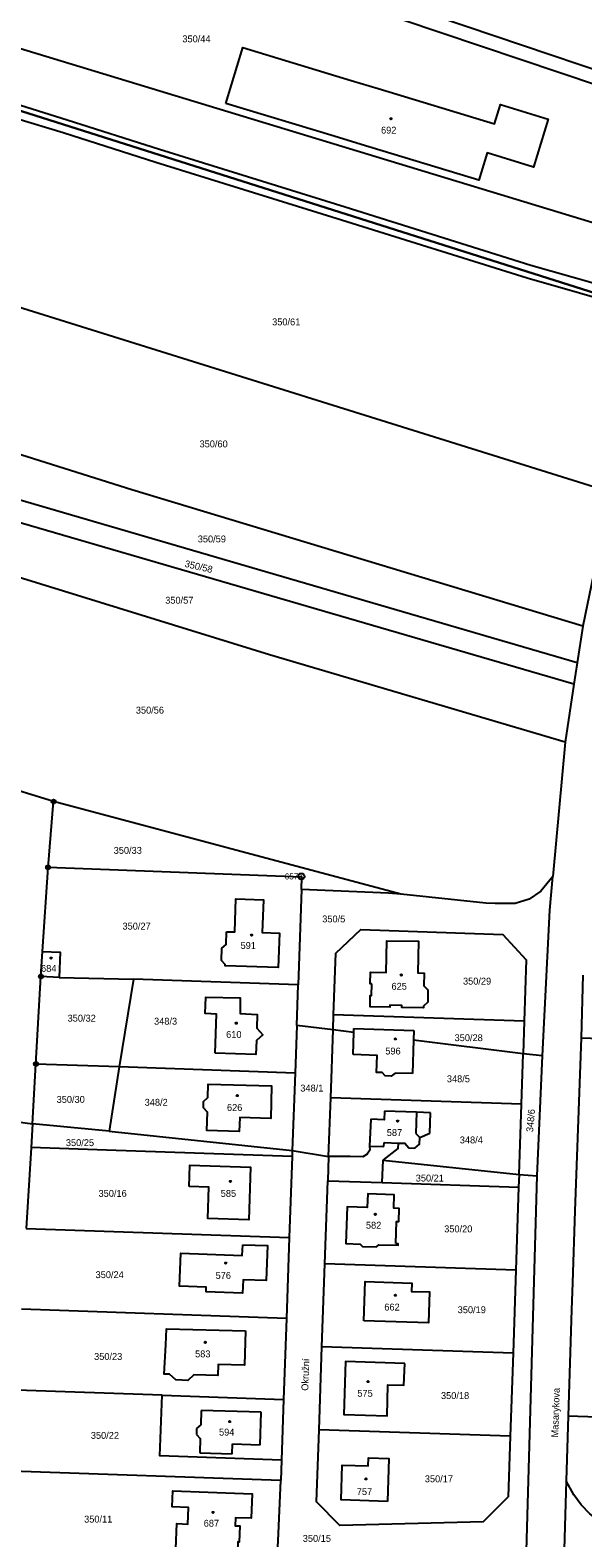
# Model space of a CAD drawing. Extents: x -758582 to -751794, y -998770 to -994350.
# Drawn here: x -756048.6 to -755912.3, y -995169.4 to -994797.3 of the extents above; entities that cross this region are included whole.
import ezdxf

# ---------------------------------------------------------------- set-up
doc = ezdxf.new("R2010")
doc.units = 0
for name, color, linetype in [('Hranice parcel', 7, 'Continuous'), ('Parcelní čísla', 7, 'Continuous'), ('Pop  PČ popisy', 7, 'Continuous'), ('Vnitřní kresba', 7, 'Continuous'), ('Věcná břemena k části', 7, 'Continuous'), ('Značky bodu BP', 7, 'Continuous'), ('Značky budov', 7, 'Continuous')]:
    doc.layers.add(name, color=color, linetype=linetype)

msp = doc.modelspace()

# ---------------------------------------------------------------- linework, layer by layer
at = {"layer": 'Hranice parcel'}
for p, q in [((-755905.48, -994911.3), (-756086.25, -994854.78)), ((-755913.68, -994953.37), (-756093.96, -994900.74)), ((-755914.5, -994958.67), (-756094.86, -994906.09)), ((-755905.48, -994911.3), (-755912.3, -994944.36)), ((-755912.3, -994944.36), (-755913.68, -994953.37)), ((-755913.68, -994953.37), (-755914.5, -994958.67)), ((-755914.5, -994958.67), (-755916.67, -994973.02)), ((-756042.86, -994987.64), (-756105.33, -994968.45)), ((-755916.67, -994973.02), (-755919.67, -995006.16)), ((-756044.23, -995003.89), (-756042.86, -994987.64)), ((-755957.2, -995010.51), (-756042.86, -994987.64)), ((-756045.56, -995024.64), (-756044.23, -995003.89)), ((-755981.6, -995006.33), (-756044.23, -995003.89)), ((-755981.7, -995009.33), (-755982.53, -995032.9)), ((-755981.7, -995009.33), (-755981.6, -995006.33)), ((-755919.67, -995006.16), (-755922.67, -995009.76)), ((-756045.98, -995030.81), (-756045.56, -995024.64)), ((-756047.22, -995052.41), (-756045.98, -995030.81)), ((-756041.52, -995031.03), (-756045.98, -995030.81)), ((-756041.52, -995031.03), (-756023.16, -995031.47)), ((-756023.16, -995031.47), (-756026.66, -995053.14)), ((-755982.53, -995032.9), (-756023.16, -995031.47)), ((-755912.26, -995030.46), (-755912.72, -995045.92)), ((-755982.88, -995042.87), (-755982.53, -995032.9)), ((-755982.88, -995042.87), (-755983.29, -995054.66)), ((-755973.91, -995043.99), (-755982.88, -995042.87)), ((-755973.91, -995043.99), (-755973.78, -995040.24)), ((-755926.77, -995041.81), (-755973.78, -995040.24)), ((-755926.77, -995041.81), (-755927.04, -995049.89)), ((-755974.49, -995060.72), (-755973.91, -995043.99)), ((-755968.8, -995044.63), (-755973.91, -995043.99)), ((-755968.98, -995050.08), (-755968.8, -995044.63)), ((-755968.8, -995044.63), (-755968.77, -995043.68)), ((-755968.77, -995043.68), (-755953.96, -995044.17)), ((-755954.04, -995046.49), (-755954.32, -995054.78)), ((-755953.96, -995044.17), (-755954.04, -995046.49)), ((-755927.04, -995049.89), (-755954.04, -995046.49)), ((-755927.45, -995062.29), (-755927.04, -995049.89)), ((-755922.21, -995050.42), (-755927.04, -995049.89)), ((-755923.55, -995079.97), (-755922.21, -995050.42)), ((-756048.07, -995067.15), (-756047.22, -995052.41)), ((-756026.66, -995053.14), (-756047.22, -995052.41)), ((-756026.66, -995053.14), (-756029.12, -995068.97)), ((-755983.29, -995054.66), (-756026.66, -995053.14)), ((-755983.29, -995054.66), (-755983.96, -995073.75)), ((-755975, -995075.23), (-755974.49, -995060.72)), ((-755927.45, -995062.29), (-755974.49, -995060.72)), ((-756082.85, -995062.35), (-756048.07, -995067.15)), ((-755950.03, -995069.45), (-755949.86, -995064.47)), ((-755928.03, -995079.68), (-755927.45, -995062.29)), ((-756048.07, -995067.15), (-756048.42, -995072.99)), ((-756029.12, -995068.97), (-756048.07, -995067.15)), ((-756029.12, -995068.97), (-755983.96, -995073.75)), ((-756048.42, -995072.99), (-756049.59, -995092.97)), ((-756029.84, -995073.65), (-756048.42, -995072.99)), ((-755984.01, -995075.25), (-756029.84, -995073.65)), ((-755984.01, -995075.25), (-755984.71, -995095.24)), ((-755983.96, -995073.75), (-755984.01, -995075.25)), ((-755983.96, -995073.75), (-755975, -995075.23)), ((-755975, -995075.23), (-755975.21, -995081.21)), ((-755969.65, -995075.27), (-755975, -995075.23)), ((-755961.8, -995081.66), (-755961.51, -995076.13)), ((-755961.51, -995076.13), (-755928.03, -995079.68)), ((-755928.03, -995079.68), (-755928.14, -995082.78)), ((-755928.03, -995079.68), (-755923.55, -995079.97)), ((-755926.14, -995172.57), (-755923.55, -995079.97)), ((-755975.93, -995101.7), (-755975.21, -995081.21)), ((-755975.21, -995081.21), (-755961.8, -995081.66)), ((-755961.8, -995081.66), (-755928.14, -995082.78)), ((-755928.14, -995082.78), (-755928.82, -995103.27)), ((-756049.59, -995092.97), (-755984.71, -995095.24)), ((-755984.71, -995095.24), (-755985.41, -995115.23)), ((-755976.65, -995122.19), (-755975.93, -995101.7)), ((-755928.82, -995103.27), (-755975.93, -995101.7)), ((-755928.82, -995103.27), (-755929.51, -995123.76)), ((-755985.41, -995115.23), (-756050.77, -995112.94)), ((-755915.05, -995113.11), (-755915.89, -995139.2)), ((-755985.41, -995115.23), (-755986.11, -995135.21)), ((-755977.36, -995142.67), (-755976.65, -995122.19)), ((-755929.51, -995123.76), (-755976.65, -995122.19)), ((-755929.51, -995123.76), (-755930.19, -995144.25)), ((-756016.09, -995134.16), (-756051.95, -995132.91)), ((-756016.09, -995134.16), (-755986.11, -995135.21)), ((-755986.11, -995135.21), (-755986.64, -995150.2)), ((-755915.89, -995139.2), (-755916.41, -995155.24)), ((-755915.89, -995139.2), (-755873.79, -995140.68)), ((-755930.19, -995144.25), (-755977.36, -995142.67)), ((-755986.64, -995150.2), (-755986.81, -995155.2)), ((-755986.81, -995155.2), (-756053.13, -995152.88)), ((-755916.41, -995155.24), (-755917.23, -995182.52))]:
    msp.add_line(p, q, dxfattribs=at)
for points in [[(-756070.72, -994760.05), (-756053.87, -994764.58), (-756035.07, -994770.23), (-756011.64, -994777.98), (-755956.83, -994794.65), (-755879.3, -994820.73)], [(-755878.36, -994817.53), (-755955, -994791.7), (-756000, -994778.26)], [(-756071.25, -994800.04), (-756053.14, -994801.16), (-755892.22, -994850.06), (-755894.52, -994857.69)], [(-756000.4, -994815.33), (-755996.2, -994801.53), (-755969.41, -994809.67), (-755962.8, -994811.63), (-755934.07, -994820.38), (-755932.63, -994815.64), (-755920.84, -994819.2), (-755924.45, -994831.07), (-755935.89, -994827.57), (-755937.92, -994834.32), (-755966.99, -994825.48), (-755973.63, -994823.43), (-756000.4, -994815.33)], [(-756073.22, -994814.18), (-756055.93, -994815.59), (-755897.05, -994866.03)], [(-755912.3, -994944.36), (-756023.52, -994910.68), (-756092.02, -994889.17)], [(-755916.67, -994973.02), (-755989.55, -994951.4), (-756096.9, -994918.28)], [(-755957.2, -995010.51), (-755960.22, -995010.26), (-755981.7, -995009.33)], [(-755922.21, -995050.42), (-755920.42, -995014.42), (-755919.67, -995006.16)], [(-756000.2, -995019.75), (-755998.17, -995019.8), (-755997.9, -995011.67), (-755991.08, -995011.89), (-755991.39, -995019.98), (-755987.1, -995020.12), (-755987.45, -995028.62), (-756000.5, -995028.21), (-756000.5, -995027.84), (-756001.45, -995026.87), (-756001.34, -995023.84), (-756000.32, -995022.88), (-756000.2, -995019.75)], [(-755933.94, -995012.83), (-755936.2, -995012.74), (-755957.2, -995010.51)], [(-755922.67, -995009.76), (-755925.49, -995011.71), (-755928.98, -995012.76), (-755933.94, -995012.83)], [(-755973.78, -995040.24), (-755973.25, -995025.04), (-755967.04, -995019.25), (-755932.06, -995020.48), (-755926.27, -995026.69), (-755926.77, -995041.81)], [(-755964.35, -995032.62), (-755964.73, -995032.61), (-755964.67, -995029.77), (-755960.82, -995029.84), (-755960.67, -995021.99), (-755952.83, -995022.11), (-755952.97, -995029.94), (-755951.44, -995029.99), (-755951.47, -995033.09), (-755950.5, -995034.11), (-755950.56, -995037.17), (-755951.57, -995038.16), (-755951.62, -995038.56), (-755956.94, -995038.46), (-755956.93, -995037.96), (-755959.93, -995037.9), (-755959.94, -995038.41), (-755964.77, -995038.32), (-755964.77, -995035.48), (-755964.4, -995035.49), (-755964.35, -995032.62)], [(-756045.56, -995024.64), (-756041.21, -995024.77), (-756041.52, -995031.03)], [(-756002.98, -995049.76), (-756002.65, -995040.07), (-756005.44, -995039.97), (-756005.3, -995035.88), (-755996.81, -995036.11), (-755996.82, -995039.91), (-755992.6, -995040.16), (-755992.71, -995043.59), (-755991.23, -995045.18), (-755992.83, -995046.61), (-755992.98, -995050.1), (-756002.98, -995049.76)], [(-755912.72, -995045.92), (-755914.22, -995088.61), (-755914.79, -995106.38), (-755915.05, -995113.11)], [(-755912.72, -995045.92), (-755864.72, -995047.59), (-755864.78, -995051.19), (-755864.49, -995051.21), (-755864.67, -995056.14)], [(-755954.32, -995054.78), (-755958.61, -995054.65), (-755959.55, -995055.44), (-755961.09, -995055.36), (-755961.83, -995054.54), (-755963.17, -995054.5), (-755963.01, -995050.3), (-755968.98, -995050.08)], [(-756005.84, -995061.68), (-756004.79, -995060.67), (-756004.71, -995057.36), (-755989.08, -995057.82), (-755989.29, -995065.83), (-755996.94, -995065.63), (-755997.04, -995069.09), (-756005.03, -995068.86), (-756004.89, -995064.28), (-756005.9, -995063.23), (-756005.84, -995061.68)], [(-755961.25, -995064.05), (-755961.33, -995066.2), (-755964.59, -995066.05)], [(-755949.86, -995064.47), (-755953.32, -995064.3), (-755961.25, -995064.05)], [(-755964.59, -995066.05), (-755964.89, -995072.65), (-755964.87, -995073.69)], [(-755961.51, -995076.13), (-755957.86, -995073.27), (-755957.75, -995071.91), (-755956.19, -995071.97), (-755955.2, -995073.1), (-755953.73, -995073.19), (-755952.56, -995072.18), (-755952.51, -995070.58), (-755950.03, -995069.45)], [(-755964.87, -995073.69), (-755965.52, -995074.64), (-755966.54, -995075.29), (-755969.65, -995075.27)], [(-756009.43, -995082.62), (-756009.27, -995077.37), (-755994.27, -995077.84), (-755994.69, -995090.84), (-756004.79, -995090.51), (-756004.54, -995082.77), (-756009.43, -995082.62)], [(-755958.46, -995096.73), (-755958.28, -995091.3), (-755957.68, -995091.31), (-755957.59, -995088.06), (-755958.91, -995088.01), (-755958.79, -995084.7), (-755965.35, -995084.46), (-755965.47, -995087.82), (-755970.44, -995087.68), (-755970.72, -995096.73), (-755967.22, -995096.84), (-755966.65, -995097.48), (-755963.21, -995097.55), (-755962.6, -995097), (-755957.86, -995097.13), (-755957.83, -995096.76), (-755958.46, -995096.73)], [(-755996.15, -995097.05), (-755990.09, -995097.23), (-755990.39, -995105.86), (-755996.09, -995105.67), (-755996.21, -995108.98), (-756005.2, -995108.64), (-756005.23, -995107.46), (-756011.83, -995107.26), (-756011.44, -995099.1), (-755996.31, -995099.64), (-755996.15, -995097.05)], [(-755966.3, -995115.77), (-755965.97, -995106.08), (-755954.48, -995106.46), (-755954.55, -995108.52), (-755950.09, -995108.67), (-755950.34, -995116.27), (-755966.3, -995115.77)], [(-755995.54, -995118.25), (-755995.77, -995126.77), (-756002.23, -995126.56), (-756002.3, -995129.27), (-756008.24, -995129.08), (-756009.76, -995130.48), (-756012.72, -995130.37), (-756014.3, -995128.99), (-756015.54, -995128.93), (-756015.2, -995121.74), (-756015.01, -995117.74), (-755995.54, -995118.25)], [(-755956.23, -995126.3), (-755970.82, -995125.79), (-755971.28, -995138.88), (-755960.58, -995139.26), (-755960.36, -995131.56), (-755956.42, -995131.7), (-755956.23, -995126.3)], [(-755986.64, -995150.2), (-756016.62, -995149.15), (-756016.09, -995134.16)], [(-755930.19, -995144.25), (-755930.69, -995159.24), (-755936.89, -995165.39), (-755972.2, -995166.3), (-755977.99, -995160.45), (-755977.36, -995142.67)], [(-755960.44, -995160.35), (-755971.91, -995159.97), (-755971.62, -995151.4), (-755965.23, -995151.61), (-755965.15, -995149.61), (-755960.11, -995149.78), (-755960.44, -995160.35)], [(-755997.45, -995172.6), (-756012.67, -995172.09), (-756012.43, -995165.84), (-756009.72, -995165.96), (-756009.61, -995161.83), (-756013.57, -995161.66), (-756013.41, -995157.77), (-755993.9, -995158.49), (-755994.14, -995164.48), (-755998.01, -995164.39), (-755998.09, -995166.39), (-755996.92, -995166.38), (-755997.07, -995170.42), (-755997.39, -995170.37), (-755997.45, -995172.6)], [(-755987.66, -995174.35), (-755987.47, -995170.05), (-755986.81, -995155.2)], [(-755873.57, -995167.83), (-755897.54, -995166.95), (-755902.48, -995166.96), (-755905.5, -995166.53), (-755908.25, -995165.22), (-755910.54, -995163.41), (-755912.73, -995161.19), (-755914.52, -995158.71), (-755916.41, -995155.24)]]:
    msp.add_lwpolyline(points, dxfattribs=at)
at = {"layer": 'Vnitřní kresba'}
for p, q in [((-755953.32, -995064.3), (-755953.49, -995069.54)), ((-755964.89, -995072.65), (-755961.35, -995072.76)), ((-755961.35, -995072.76), (-755961.32, -995071.77)), ((-755961.32, -995071.77), (-755957.75, -995071.91)), ((-755953.49, -995069.54), (-755952.51, -995070.58)), ((-756006.45, -995137.92), (-756006.57, -995141.44)), ((-755991.66, -995138.36), (-756006.45, -995137.92)), ((-755991.91, -995146.36), (-755991.66, -995138.36)), ((-756007.59, -995142.37), (-756007.63, -995143.85)), ((-756006.57, -995141.44), (-756007.59, -995142.37)), ((-756007.63, -995143.85), (-756006.67, -995144.85)), ((-756006.67, -995144.85), (-756006.78, -995148.38)), ((-755998.8, -995148.63), (-755998.7, -995146.16)), ((-755998.7, -995146.16), (-755991.91, -995146.36)), ((-756006.78, -995148.38), (-755998.8, -995148.63))]:
    msp.add_line(p, q, dxfattribs=at)
at = {"layer": 'Věcná břemena k části'}
for points in [[(-756088.72, -994825.18), (-756088.76, -994828.38), (-756079.17, -994829.59), (-756073.22, -994814.18), (-756055.93, -994815.59), (-755897.05, -994866.03), (-755893.83, -994867.05), (-755893.03, -994864.4), (-755896.29, -994863.5), (-755899.3, -994862.67), (-755925.08, -994855.31), (-755970.88, -994840.97), (-756016.69, -994826.72), (-756039.51, -994819.46), (-756051.05, -994815.89), (-756057.79, -994814.43), (-756063.16, -994813.8), (-756074.11, -994813.66), (-756078.96, -994825.73), (-756079.69, -994826.35)], [(-755893.95, -994867.51), (-755893.83, -994867.05), (-755897.05, -994866.03), (-756055.93, -994815.59), (-756073.22, -994814.18), (-756079.17, -994829.59), (-756078.6, -994829.66), (-756076.25, -994827.69), (-756071.94, -994816.93), (-756063.37, -994817.04), (-756058.32, -994817.63), (-756051.89, -994819.03), (-756040.48, -994822.55), (-756017.66, -994829.81), (-755971.85, -994844.06), (-755926.01, -994858.42), (-755900.18, -994865.79)]]:
    msp.add_lwpolyline(points, close=True, dxfattribs=at)
at = {"layer": 'Značky bodu BP'}
for centre, radius in [((-756042.86, -994987.64), 0.5), ((-756042.86, -994987.64), 0.0303), ((-756044.23, -995003.89), 0.5), ((-756044.23, -995003.89), 0.0303), ((-755981.73, -995006.11), 0.75), ((-755981.73, -995006.11), 0.03), ((-756045.98, -995030.81), 0.5), ((-756045.98, -995030.81), 0.0303), ((-756047.22, -995052.41), 0.5), ((-756047.22, -995052.41), 0.0303)]:
    msp.add_circle(centre, radius, dxfattribs=at)
at = {"layer": 'Značky budov'}
for centre in [(-755959.63, -994819.12), (-755994.02, -995020.61), (-756043.47, -995026.26), (-755957.1, -995030.45), (-755997.81, -995042.33), (-755958.51, -995046.2), (-755997.54, -995060.19), (-755957.97, -995066.5), (-755999.23, -995081.39), (-755963.48, -995089.51), (-756000.38, -995101.55), (-755958.53, -995109.47), (-756005.44, -995121.09), (-755965.25, -995130.79), (-755999.4, -995140.64), (-755965.81, -995154.79), (-756003.5, -995163.07)]:
    msp.add_circle(centre, 0.175, dxfattribs=at)

# ---------------------------------------------------------------- texts
at = {"layer": 'Parcelní čísla'}
for s, p in [('350/44', (-756011.09, -994800.26)), ('692', (-755962.07, -994822.79)), ('350/61', (-755988.94, -994870.11)), ('350/60', (-756006.85, -994900.22)), ('350/59', (-756007.29, -994923.68)), ('350/57', (-756015.32, -994938.8)), ('350/56', (-756022.57, -994965.93)), ('350/33', (-756028.04, -995000.53)), ('350/5', (-755976.58, -995017.46)), ('350/27', (-756025.86, -995019.24)), ('591', (-755996.73, -995024.01)), ('684', (-756045.95, -995029.66)), ('350/29', (-755941.85, -995032.81)), ('625', (-755959.49, -995034.08)), ('350/32', (-756039.4, -995041.95)), ('348/3', (-756018.07, -995042.7)), ('610', (-756000.29, -995045.97)), ('350/28', (-755943.92, -995046.77)), ('596', (-755961.02, -995050.06)), ('348/1', (-755981.98, -995059.2)), ('348/5', (-755945.83, -995056.91)), ('350/30', (-756042.11, -995061.99)), ('348/2', (-756020.39, -995062.71)), ('626', (-756000.08, -995063.99)), ('587', (-755960.65, -995070.18)), ('350/25', (-756039.83, -995072.67)), ('348/4', (-755942.64, -995072)), ('350/21', (-755953.51, -995081.41)), ('350/16', (-756031.77, -995085.19)), ('585', (-756001.62, -995085.19)), ('582', (-755965.8, -995093.05)), ('350/20', (-755946.49, -995093.95)), ('350/24', (-756032.5, -995105.25)), ('576', (-756002.89, -995105.44)), ('662', (-755961.26, -995113.25)), ('350/19', (-755943.16, -995113.9)), ('350/23', (-756032.87, -995125.44)), ('583', (-756007.95, -995124.8)), ('575', (-755967.91, -995134.53)), ('350/18', (-755947.28, -995135.09)), ('350/22', (-756033.67, -995144.91)), ('594', (-756002.04, -995144.12)), ('350/17', (-755951.27, -995155.64)), ('757', (-755968.05, -995158.79)), ('350/11', (-756035.33, -995165.58)), ('687', (-756005.82, -995166.6)), ('350/15', (-755981.38, -995170.34))]:
    msp.add_text(s, height=1.7, dxfattribs=at).set_placement(p)
for s, rotation, p in [('350/58', 347, (-756010.63, -994929.69)), ('348/6', 85, (-755924.56, -995069.28))]:
    msp.add_text(s, height=1.7, rotation=rotation, dxfattribs=at).set_placement(p)
at = {"layer": 'Pop  PČ popisy'}
for s, p in [('Okružní', (-755980.03, -995133.08)), ('Masarykova', (-755918.38, -995144.61))]:
    msp.add_text(s, height=1.7, rotation=88, dxfattribs=at).set_placement(p)
at = {"layer": 'Značky bodu BP'}
msp.add_text('657', height=1.5, dxfattribs=at).set_placement((-755985.83, -995006.86))

doc.saveas('drawing.dxf')
